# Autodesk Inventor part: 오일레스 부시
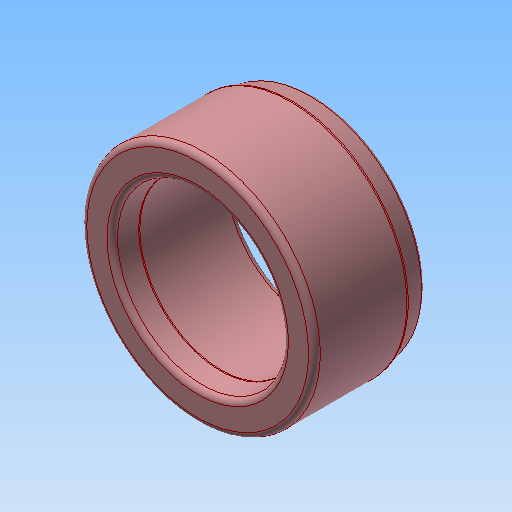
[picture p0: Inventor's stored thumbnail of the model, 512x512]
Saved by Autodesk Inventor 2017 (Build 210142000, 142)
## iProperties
Created: 2023-11
Part Number: 오일레스 부시
Material: 강철, 합금
Document SubType Name: Modeling
Designer: mdu-01
Density: 1 g/cm^3
Appearance: 기본값(1)
Author: mdu-01
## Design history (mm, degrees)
sketch "스케치1"
  geometry: L1 (7.772, 0)-(9.5, 0); L2 (10, -0.5)-(10, -7.934); L3 (9.08, -10)-(7.5, -10); L4 (7, -9.5)-(7, -2.044); L5 (0, 0)-(0, -10); L6 (9.983, -8.064)-(9.563, -9.629); L7 (7.008, -1.957)-(7.28, -0.413); A1 r 0.5 centre (9.5, -0.5) between (10, -0.5) and (9.5, 0); A2 r 0.5 centre (7.5, -9.5) between (7, -9.5) and (7.5, -10); A3 r 0.5 centre (9.08, -9.5) between (9.08, -10) and (9.563, -9.629); A4 r 0.5 centre (7.772, -0.5) between (7.772, 0) and (7.28, -0.413); A5 r 0.5 centre (7.5, -2.044) between (7.008, -1.957) and (7, -2.044); A6 r 0.5 centre (9.5, -7.934) between (9.983, -8.064) and (10, -7.934); 4 further points
  constraints: 14 end point, 12 point on circle, 12 tangent, 10 point on line, 6 centre point, 4 equal radius, 3 parallel, 1 horizontal, 1 perpendicular
  dimensions: "d0" = 10 distance of L5.start L5.end; "d1" = 14 diameter of L4 L5; "d2" = 20 diameter of L2 L5; "d3" = 0.5 radius of A1; "d4" = 2 distance of point (10, -8) point (10, -10); "d5" = 15 deg angle of L2 L6; "d6" = 2 distance of point (7, -2) point (7, 0); "d7" = 10 deg angle of L4 L7; "d8" = 0.5 radius of A3
revolve "회전1" sketch "스케치1" stored, may be unused: angle "d9" = 90 deg
node "솔리드1"
